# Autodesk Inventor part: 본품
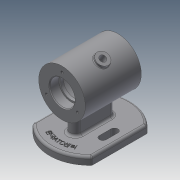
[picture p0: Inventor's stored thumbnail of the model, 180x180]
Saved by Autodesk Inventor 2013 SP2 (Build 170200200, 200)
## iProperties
Created: 2022-02
Part Number: 본품
Material: Generic
Document SubType Name: Modeling
Designer: aa
Density: 1 g/cm^3
Mass: 183.424 g
Surface Area: 489.745 cm^2
Volume: 183.424 cm^3
Author: aa
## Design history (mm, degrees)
sketch "스케치1"
  geometry: L1 (-36, 0)-(36, 0); L2 (-36, 0)-(-36, 30); L3 (-36, 30)-(36, 30); L4 (36, 30)-(36, 0); L5 (-36, 16)-(-24, 16); L6 (-24, 16)-(-24, 14); L7 (-24, 14)-(-20, 14); L8 (-20, 14)-(-20, 25); L9 (-20, 25)-(20, 25); L10 (20, 25)-(20, 14); L11 (20, 14)-(24, 14); L12 (24, 14)-(24, 16); L13 (24, 16)-(36, 16); 2 further points
  constraints: 26 end point, 7 parallel, 5 perpendicular, 2 point on line, 1 coincident, 1 horizontal, 1 midpoint
  dimensions: "d0" = 72 distance of L1.start L1.end; "d1" = 60 diameter of L3 L1; "d2" = 12 distance of L5.start L5.end; "d3" = 12 distance of L12.end L13.end; "d4" = 40 distance of L8.end L9.end; "d5" = 4 distance of L6.end L7.end; "d6" = 32 diameter of L5 L1; "d7" = 28 diameter of L7 L1; "d8" = 50 diameter of L9 L1; "d9" = 28 diameter of L11 L1; "d10" = 32 diameter of L13 L1
revolve "회전1" sketch "스케치1" stored, may be unused: angle "d11" = 90 deg
sketch "스케치2"
  geometry: C1 r 30 at (0, 0) reference; 1 further point
  constraints: 1 vertical alignment
  dimensions: "d12" = 23 distance of C1.centre point (0, 23)
hole "구멍1" sketch "스케치2" at (0, 23) diameter "d13" = 3.242; stored, may be unused: countersink angle "d17" = 90 deg, drill point angle "d19" = 118 deg; dims "d14" = 8, "d15" = 4, "d16" = 2, "d18" = 10
node "작업 평면1"
sketch "스케치3"
  geometry: L1 (35.496, -38)-(-35.496, -38); L2 (35.496, 38)-(-35.496, 38); A1 r 52 centre (0, 0) between (35.496, -38) and (35.496, 38); A2 r 52 centre (0, 0) between (-35.496, 38) and (-35.496, -38); 3 further points
  constraints: 4 end point, 4 point on circle, 2 centre point, 2 midpoint, 1 coincident, 1 horizontal, 1 parallel, 1 vertical alignment
  dimensions: "d25" = 76 distance between parallel lines of L2 L1; "d26" = 52 radius of A1; "d27" = 38 distance from line of point (0, 0) L1
extrude "돌출1" join sketch "스케치3" distance "d28" = 10; taper "d29" = 0 deg
sketch "스케치4"
  geometry: L1 (-19, 7)-(19, 7); L2 (19, 7)-(19, -7); L3 (19, -7)-(-19, -7); L4 (-19, -7)-(-19, 7); L5 (-19, 7)-(19, -7); L6 (19, 7)-(-19, -7); A1 r 52 centre (0, 0) between (35.496, -38) and (35.496, 38) reference; A2 r 7 centre (-19, 0) between (-19, 7) and (-19, -7); A3 r 7 centre (19, 0) between (19, -7) and (19, 7)
  constraints: 12 end point, 4 point on circle, 4 tangent, 2 centre point, 2 midpoint, 2 parallel, 1 horizontal, 1 perpendicular
  dimensions: "d30" = 38 distance of L2.end L3.end; "d31" = 14 distance of L1.end L2.end
extrude "돌출2" join sketch "스케치4" stored distance "d32" = 10; taper "d33" = 0 deg
sketch "스케치5"
  geometry: L1 (-7.5, 28.5)-(7.5, 28.5); L2 (7.5, 28.5)-(7.5, 19.5); L3 (7.5, 19.5)-(-7.5, 19.5); L4 (-7.5, 19.5)-(-7.5, 28.5); L5 (-7.5, 28.5)-(7.5, 19.5); L6 (7.5, 28.5)-(-7.5, 19.5); A1 r 52 centre (0, 0) between (-35.496, 38) and (-35.496, -38) reference; A2 r 4.5 centre (-7.5, 24) between (-7.5, 28.5) and (-7.5, 19.5); A3 r 4.5 centre (7.5, 24) between (7.5, 19.5) and (7.5, 28.5); 2 further points
  constraints: 12 end point, 4 point on circle, 4 tangent, 3 midpoint, 2 centre point, 2 parallel, 1 horizontal, 1 perpendicular, 1 vertical alignment
  dimensions: "d34" = 15 distance of L2.end L3.end; "d35" = 9 distance of L1.end L2.end; "d36" = 24 distance of A1.centre point (0, 24)
extrude "돌출3" cut sketch "스케치5" stored distance "d37" = 10; taper "d38" = 0 deg
sketch "스케치6"
  geometry: L1 (-29.172, -7)-(-52, -7) reference; L2 (-52, -7)-(-52, -19.5) reference; L3 (-52, -19.5)-(-62, -19.5) reference; L4 (-62, -19.5)-(-62, 19.5) reference; L5 (-62, 19.5)-(-52, 19.5) reference; L6 (-52, 19.5)-(-52, 7) reference; L7 (-52, 7)-(-29.172, 7) reference; L8 (-62, 38)-(-52, 38) reference; L9 (-52, 38)-(-52, 28.5) reference; L10 (-52, 28.5)-(-62, 28.5) reference; L11 (-62, 28.5)-(-62, 38) reference; L12 (-52, -38)-(-62, -38) reference; L13 (-62, -38)-(-62, -28.5) reference; L14 (-62, -28.5)-(-52, -28.5) reference; L15 (-52, -28.5)-(-52, -38) reference; L16 (0, 0)-(28.579, 16.5); L17 (0, 0)-(33, 0); C1 r 25 at (0, 0) reference; A1 r 30 centre (0, 0) between (-29.172, -7) and (-29.172, 7) reference; 2 further points
  constraints: 4 end point, 1 coincident, 1 equal length, 1 horizontal
  dimensions: "d39" = 33 distance of L16.start L16.end; "d40" = 30 deg angle of L17 L16
  node "절단 모서리 투영1"
node "작업 평면2"
sketch "스케치7"
  geometry: C1 r 8 at (0, 0); 1 further point
  constraints: 1 centre point, 1 coincident
  dimensions: "d41" = 16 diameter of C1
extrude "돌출4" join sketch "스케치7" stored distance "d42" = 10; taper "d43" = 0 deg
sketch "스케치8"
  geometry: C1 r 8 at (0, 0) reference; 1 further point
  constraints: 1 coincident
hole "구멍2" sketch "스케치8" at (0, 0) diameter "d44" = 8; stored, may be unused: countersink angle "d48" = 90 deg, drill point angle "d50" = 118 deg; dims "d45" = 8, "d46" = 4, "d47" = 2, "d49" = 10
fillet "모깎기1" dims "d51" = 3, "d52" = 0.3
chamfer "모따기1" distance "d53" = 1; stored, may be unused: second distance "d54" = 2, angle "d55" = 45 deg
fillet "모깎기2" dims "d56" = 1
fillet "모깎기3" dims "d57" = 3
fillet "모깎기4" dims "d58" = 3
fillet "모깎기5" dims "d59" = 3
sketch "스케치9"
  geometry: C1 r 42.5 at (0, 0); A1 r 49 centre (0, 0) between (34.293, -35) and (34.293, 35) reference
  constraints: 1 centre point, 1 coincident, 1 other
  dimensions: "d60" = 85 diameter of C1
feature "엠보싱1" sketch "스케치9" dims "d61" = 0.5, "d62" = 0
node "솔리드1"
pattern_circular "원형 패턴1" dims angle "d21" = 360 deg
mirror "대칭1"
mirror "대칭2"
other parameters: "d23" = -62, "d24" = 104
